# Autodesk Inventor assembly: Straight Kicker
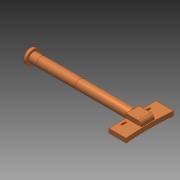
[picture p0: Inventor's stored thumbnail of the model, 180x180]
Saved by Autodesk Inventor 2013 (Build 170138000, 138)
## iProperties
Created: 2012-07
Part Number: Straight Kicker
Document SubType Name: Assembly
Designer: rYan
Mass: 68.5653 g
Surface Area: 99.7484 cm^2
Volume: 16.9829 cm^3
Density: 4.03732 g/cm^3
Author: rYan
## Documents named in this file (6)
- D:\SVN\2013\Inventor\Kicker\Straight\MG-Straight Kicker.iam
- D:\SVN\2013\Inventor\Kicker\Straight\Kicker Stoessel.ipt
- D:\SVN\2013\Inventor\Kicker\Straight\Kicker Mitte.ipt
- D:\SVN\2013\Inventor\Kicker\Straight\Kicker Hinten.ipt
- D:\SVN\2013\Inventor\Kicker\Straight\Kicker Vorne.ipt
- D:\SVN\2013\Inventor\Inhaltscenter\de-DE\ISO 10642(2)\ISO 10642  - M6  x  20.ipt
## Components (5 placed, 5 different names)
1. Kicker Stößel:1 — Passend:1, Passend:2, Passend:3, Passend:4
2. Kicker Mitte:1 — Passend:1, Passend:2, Passend:5, Passend:6
3. Kicker Hinten:1 — Passend:3, Passend:4, Passend:7, Passend:8
4. Kicker Vorne:1 — Passend:5, Passend:6
5. DIN EN ISO 10642 M6  x  20:1 — Passend:7, Passend:8
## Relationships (8: Mate 8)
- Passend:1 [Mate]: Kicker Stößel:1 ↔ Kicker Mitte:1
- Passend:2 [Mate]: Kicker Stößel:1 ↔ Kicker Mitte:1
- Passend:3 [Mate]: Kicker Stößel:1 ↔ Kicker Hinten:1
- Passend:4 [Mate]: Kicker Stößel:1 ↔ Kicker Hinten:1
- Passend:5 [Mate]: Kicker Mitte:1 ↔ Kicker Vorne:1
- Passend:6 [Mate]: Kicker Mitte:1 ↔ Kicker Vorne:1
- Passend:7 [Mate]: Kicker Hinten:1 ↔ DIN EN ISO 10642 M6  x  20:1
- Passend:8 [Mate]: Kicker Hinten:1 ↔ DIN EN ISO 10642 M6  x  20:1
